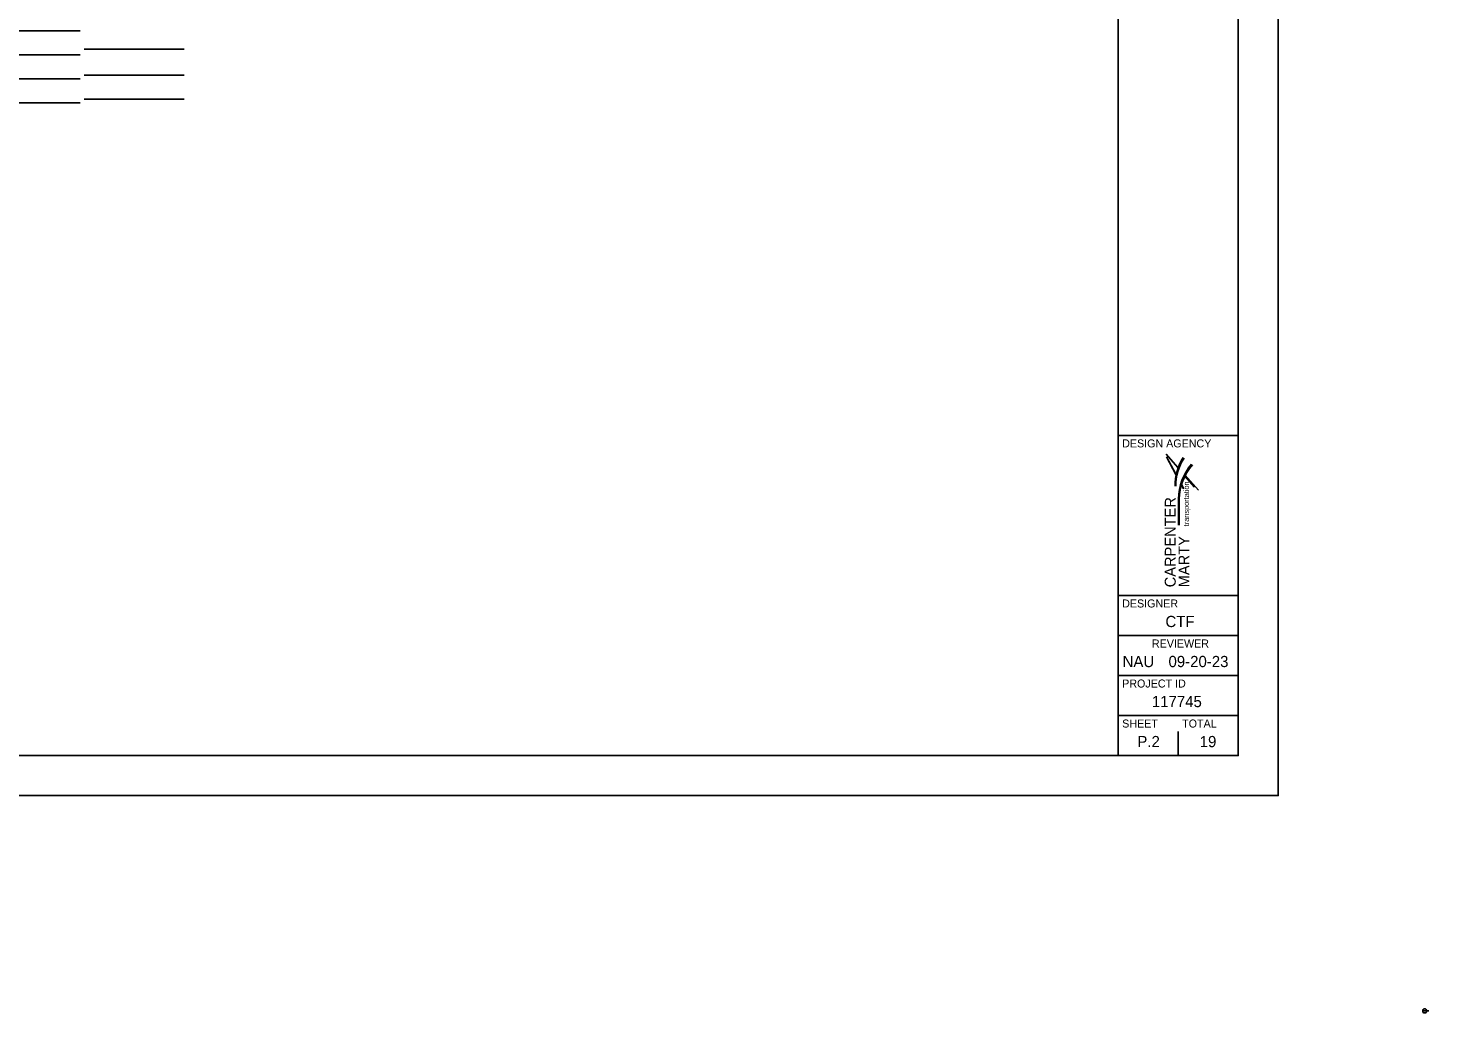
# Model space of a CAD drawing. Extents: x -38.1 to 35.9, y -2.7 to 28.5.
# Drawn here: x 18.37 to 35.88, y -2.72 to 9.59 of the extents above; entities that cross this region are included whole.
import ezdxf

# ---------------------------------------------------------------- set-up
doc = ezdxf.new("R2010")
doc.units = 0
for name, color, linetype in [('SH_Border', 7, 'Continuous'), ('SH_Cut_Line', 7, 'Continuous'), ('SH_Data', 7, 'Continuous'), ('SH_Text', 7, 'Continuous')]:
    doc.layers.add(name, color=color, linetype=linetype)

msp = doc.modelspace()

# ---------------------------------------------------------------- linework, layer by layer
at = {"layer": 'SH_Border'}
for p, q in [((19.024, 9.553), (14.943, 9.553)), ((20.324, 9.326), (19.074, 9.326)), ((19.024, 9.253), (14.653, 9.253)), ((19.024, 8.953), (16.069, 8.953)), ((20.324, 8.999), (19.074, 8.999)), ((19.024, 8.653), (14.671, 8.653)), ((20.324, 8.699), (19.074, 8.699)), ((32.75, 3.5), (32.75, 3.5)), ((32.75, 0.5), (32.75, 0.8)), ((32.375, 0.675), (32.375, 0.675))]:
    msp.add_line(p, q, dxfattribs=at)
at = {"layer": 'SH_Cut_Line'}
msp.add_lwpolyline([(0, 0), (34, 0), (34, 22), (0, 22)], close=True, dxfattribs=at)
at = {"layer": 'SH_Data'}
for p, q in [((32.721, 4.016), (32.602, 4.232)), ((32.811, 3.84), (32.79, 3.88)), ((32.82, 3.834), (32.791, 3.886)), ((32.952, 3.853), (32.834, 3.991)), ((32.839, 4.002), (33.006, 3.816)), ((32.755, 3.378), (32.755, 3.704)), ((32.762, 3.378), (32.762, 3.704)), ((35.806, -2.69), (35.858, -2.69)), ((35.832, -2.69), (35.885, -2.69))]:
    msp.add_line(p, q, dxfattribs=at)
for points in [[(32.746, 4.104), (32.601, 4.266)], [(32.601, 4.266), (32.744, 4.098)], [(32.721, 4.016), (32.602, 4.232)], [(32.602, 4.232), (32.719, 4.011)]]:
    msp.add_lwpolyline(points, dxfattribs=at)
msp.add_circle((35.832, -2.69), 0.026, dxfattribs=at)
for centre, radius, start, end in [((33.432, 3.86), 0.721, 149.5704, 179.5529), ((33.373, 3.862), 0.654, 147.1423, 179.6525), ((33.426, 3.704), 0.671, 139.2898, 180.0106), ((33.433, 3.688), 0.672, 138.5126, 178.6075)]:
    msp.add_arc(centre, radius, start, end, dxfattribs=at)
at = {"layer": 'SH_Text'}
for p, q in [((32, 0.5), (32, 21.5)), ((32, 4.5), (33.5, 4.5)), ((32, 2.5), (33.5, 2.5)), ((32, 2), (33.5, 2)), ((32, 1.5), (33.5, 1.5)), ((32, 1), (33.5, 1))]:
    msp.add_line(p, q, dxfattribs=at)
msp.add_lwpolyline([(1.5, 21.5), (33.5, 21.5), (33.5, 0.5), (1.5, 0.5)], close=True, dxfattribs=at)

# ---------------------------------------------------------------- texts
at = {"layer": 'SH_Border'}
for s, height, p in [('DESIGN AGENCY', 0.1, (32.05, 4.35)), ('DESIGNER', 0.1, (32.05, 2.35)), ('CTF', 0.14, (32.591, 2.105)), ('REVIEWER', 0.1, (32.422, 1.85)), ('NAU', 0.14, (32.055, 1.605)), ('09-20-23', 0.14, (32.629, 1.605)), ('PROJECT ID', 0.1, (32.05, 1.35)), ('117745', 0.14, (32.421, 1.105)), ('SHEET', 0.1, (32.05, 0.85)), ('TOTAL', 0.1, (32.8, 0.85)), ('P.2', 0.14, (32.24, 0.605)), ('19', 0.14, (33.019, 0.605))]:
    msp.add_text(s, height=height, dxfattribs=at).set_placement(p)
at = {"layer": 'SH_Data'}
for s, height, p in [('transportation', 0.06649, (32.885, 3.364)), ('CARPENTER ', 0.1367, (32.719, 2.602)), ('MARTY', 0.1367, (32.891, 2.602))]:
    msp.add_text(s, height=height, rotation=90, dxfattribs=at).set_placement(p)
for s, p in [('P.2', (35.829, -2.7)), ('2', (35.831, -2.683)), ('Drawing-1', (35.864, -2.683)), ('1:1', (35.864, -2.7))]:
    msp.add_text(s, height=0.00328, dxfattribs=at).set_placement(p)

doc.saveas('drawing.dxf')
